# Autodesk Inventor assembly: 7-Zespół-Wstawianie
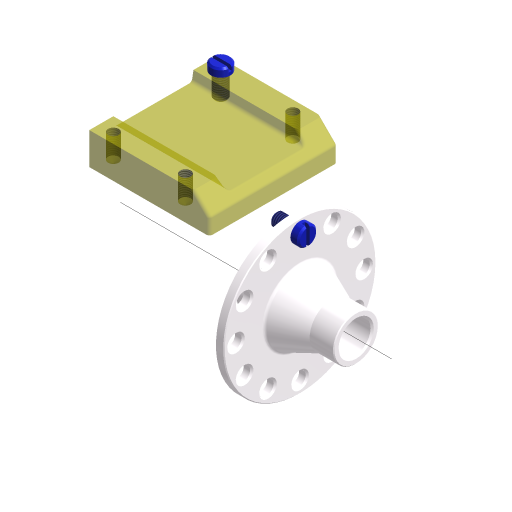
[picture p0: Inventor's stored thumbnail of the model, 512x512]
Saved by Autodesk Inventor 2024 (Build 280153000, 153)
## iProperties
Created: 2023-03
Part Number: 7-Zespół-Wstawianie
Document SubType Name: Assembly
Designer: Andrzej Jaskulski
Checked By: A.J.
Engr Approved By: Andrzej Jaskulski
Mfg Approved By: Andrzej Jaskulski
Authority: A.J.
Company: ATC
Control State: 0
Master: False
Checked Out: False
Shininess: 20.0
Length Units: 11269
Angle Units: 11279
Time Units: 11290
Mass Units: 11283
Length Display Precision: 3
Angle Display Precision: 2
Compacted: True
Density: 0.0
Volumn: 0.0
Area: 0.0
PropertySet Name: Model Information
Title: A.J.: Kurs R2024-MEP
Author: Andrzej Jaskulski
Revision Number: 1/24
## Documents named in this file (4)
- C:\Users\AndJas\Documents\R2024-MEP\Obszar roboczy\7-Zespół-Wstawianie.iam
- C:\Users\AndJas\Documents\R2024-MEP\Obszar roboczy\T.ipt
- C:\Users\AndJas\Documents\R2024-MEP\Obszar roboczy\P.ipt
- C:\Users\AndJas\Documents\R2024-MEP\Obszar roboczy\W.ipt
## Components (4 placed, 3 different names)
1. T:1 — Wstaw:2
2. P:1 — Wstawiające:1
3. W:1 — Wstawiające:1
4. W:2 — Wstaw:2
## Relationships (2: Insert 2)
- Wstawiające:1 [Insert]: P:1 ↔ W:1
- Wstaw:2 [Insert]: T:1 ↔ W:2
